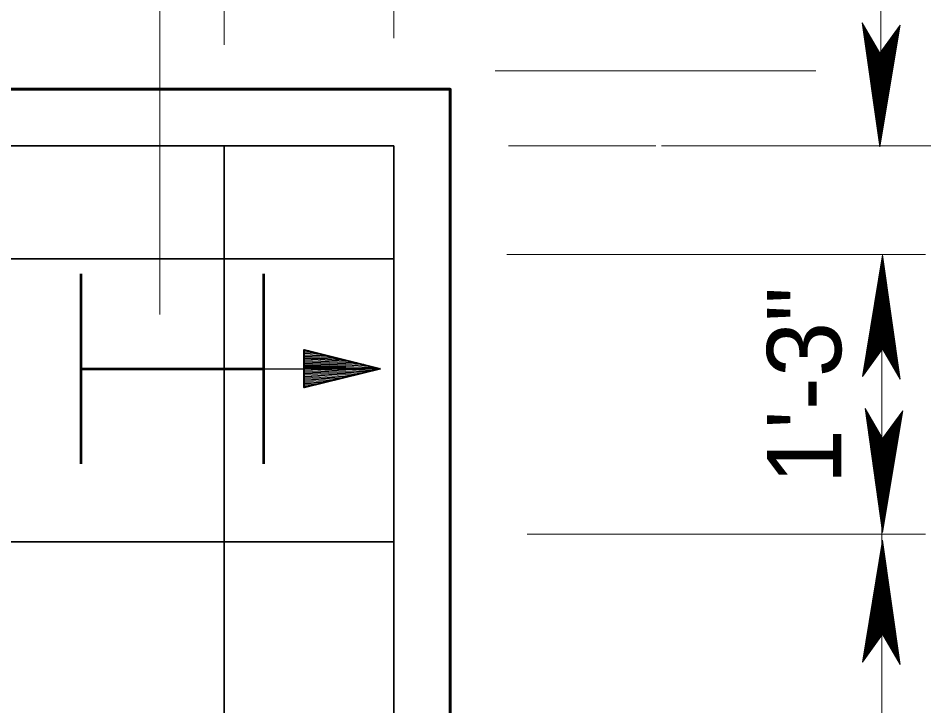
# Model space of a CAD drawing. Extents: x 144 to 252, y 360 to 425.
# Drawn here: x 178.494 to 182.528, y 377.06 to 380.098 of the extents above; entities that cross this region are included whole.
import ezdxf
from ezdxf.enums import TextEntityAlignment as Align

# ---------------------------------------------------------------- set-up
doc = ezdxf.new("R2010")
doc.units = 0
doc.header["$LTSCALE"] = 0.13
for name, color, linetype, lineweight in [('1', 7, 'Continuous', 40), ('10', 7, 'Continuous', 35), ('16', 7, 'Continuous', 13), ('3', 7, 'Continuous', 13), ('9', 7, 'Continuous', 25)]:
    doc.layers.add(name, color=color, linetype=linetype, lineweight=lineweight)

msp = doc.modelspace()

# ---------------------------------------------------------------- linework, layer by layer
at = {"layer": '1', "lineweight": 13}
for p, q in [((182.3068, 379.6502), (182.3068, 380.8135)), ((182.3109, 379.5948), (182.3109, 379.9001)), ((182.0191, 379.866), (180.6024, 379.866)), ((181.3125, 379.5348), (180.6607, 379.5348)), ((182.5277, 379.5348), (181.3369, 379.5348)), ((182.5048, 379.0537), (180.6533, 379.0537)), ((182.3109, 377.2068), (182.3109, 379.0183)), ((182.5048, 377.8178), (180.7443, 377.8178)), ((182.3109, 377.2068), (182.3109, 375.7844))]:
    msp.add_line(p, q, dxfattribs=at)
at = {"layer": '1', "lineweight": 60}
for p, q in [((156.4041, 379.7844), (180.4041, 379.7844)), ((156.4041, 379.7844), (180.4041, 379.7844)), ((156.4041, 379.7844), (180.4041, 379.7844)), ((156.4041, 379.7844), (180.4041, 379.7844)), ((180.4041, 379.7844), (180.4041, 377.2068)), ((180.4041, 379.7844), (180.4041, 377.2068)), ((180.4041, 375.7844), (180.4041, 377.2068))]:
    msp.add_line(p, q, dxfattribs=at)
at = {"layer": '1', "lineweight": 35}
for p, q in [((168.4963, 379.5344), (180.1541, 379.5344)), ((179.4041, 377.2068), (179.4041, 379.5344)), ((168.5137, 379.0344), (180.1541, 379.0344)), ((168.5137, 377.7844), (180.1541, 377.7844)), ((179.4041, 377.2068), (179.4041, 375.7844))]:
    msp.add_line(p, q, dxfattribs=at)
at = {"layer": '1', "lineweight": 53}
for p, q in [((178.7721, 378.1291), (178.7721, 378.9687)), ((179.5804, 378.1292), (179.5804, 378.9688)), ((178.7721, 378.5489), (179.5804, 378.5489))]:
    msp.add_line(p, q, dxfattribs=at)
at = {"layer": '1', "lineweight": 25}
msp.add_line((179.5804, 378.5489), (180.0804, 378.5489), dxfattribs=at)
at = {"layer": '1', "lineweight": 60}
msp.add_lwpolyline([(156.4041, 379.7844), (180.4041, 379.7844), (180.4041, 369.7844)], dxfattribs=at)
at = {"layer": '1', "lineweight": 35}
msp.add_lwpolyline([(180.1541, 375.7844), (180.1541, 377.2068), (180.1541, 379.5344)], dxfattribs=at)
at = {"layer": '10'}
for p, q in [((179.7583, 378.5971), (179.9308, 378.5898)), ((179.9422, 378.5643), (179.7583, 378.5719)), ((179.9421, 378.5579), (179.7583, 378.5657)), ((179.7583, 378.5593), (179.9419, 378.5517)), ((179.9417, 378.5454), (179.7583, 378.5531)), ((179.7583, 378.5493), (180.0935, 378.5493))]:
    msp.add_line(p, q, dxfattribs=at)
for points in [[(179.7583, 378.4658), (179.7583, 378.6327), (180.0935, 378.5494)], [(179.7583, 378.4658), (180.0935, 378.5494), (179.7583, 378.4658)]]:
    msp.add_lwpolyline(points, dxfattribs=at)
msp.add_lwpolyline([(180.0935, 378.5494), (179.7583, 378.4658), (179.7583, 378.6327), (179.7583, 378.4658)], close=True, dxfattribs=at)
at = {"layer": '3'}
for p, q in [((179.1199, 378.7893), (179.1199, 381.2715)), ((179.4041, 379.9803), (179.4041, 381.191)), ((180.1541, 380.0104), (180.1541, 380.8482)), ((182.2248, 380.0777), (182.3026, 379.529)), ((182.3028, 379.9442), (182.2248, 380.0777)), ((182.2283, 380.0718), (182.3032, 379.5434)), ((182.2303, 380.0682), (182.3032, 379.5542)), ((182.233, 380.0637), (182.3032, 379.5687)), ((182.2354, 380.0596), (182.3032, 379.5814)), ((182.2354, 380.0596), (182.3032, 379.5814)), ((182.2376, 380.0559), (182.3032, 379.5927)), ((182.3026, 379.529), (182.3918, 380.0667)), ((182.3918, 380.0667), (182.3028, 379.9442)), ((182.3032, 379.5434), (182.3895, 380.0634)), ((182.3032, 379.5542), (182.3872, 380.0602)), ((182.3032, 379.5687), (182.384, 380.0559)), ((182.3032, 379.5814), (182.3813, 380.0522)), ((182.2403, 380.0513), (182.3032, 379.6072)), ((182.2427, 380.0472), (182.3032, 379.6199)), ((182.2452, 380.0428), (182.3032, 379.6337)), ((182.2477, 380.0384), (182.3032, 379.6475)), ((182.2502, 380.0342), (182.3032, 379.6608)), ((182.2529, 380.0297), (182.3032, 379.6747)), ((182.2552, 380.0257), (182.3032, 379.6873)), ((182.2574, 380.0219), (182.3032, 379.6987)), ((182.2602, 380.0169), (182.3032, 379.7143)), ((182.2629, 380.0125), (182.3032, 379.7282)), ((182.3032, 379.5927), (182.3789, 380.0488)), ((182.3032, 379.6072), (182.3757, 380.0446)), ((182.3032, 379.6199), (182.373, 380.0408)), ((182.3032, 379.6337), (182.3701, 380.0367)), ((182.3032, 379.6475), (182.3671, 380.0327)), ((182.3032, 379.6608), (182.3642, 380.0288)), ((182.3032, 379.6747), (182.3612, 380.0247)), ((182.3032, 379.6873), (182.3586, 380.0209)), ((182.3032, 379.6987), (182.3561, 380.0175)), ((182.3032, 379.7143), (182.3527, 380.0129)), ((182.2652, 380.0085), (182.3022, 379.7477)), ((182.2671, 380.0053), (182.3038, 379.7462)), ((182.2697, 380.0009), (182.3038, 379.7601)), ((182.2722, 379.9967), (182.3038, 379.7732)), ((182.273, 379.9952), (182.3032, 379.7823)), ((182.2752, 379.9912), (182.3032, 379.7943)), ((182.2779, 379.9868), (182.3032, 379.8082)), ((182.2807, 379.9818), (182.3032, 379.8238)), ((182.2832, 379.9778), (182.3032, 379.8364)), ((182.2857, 379.9735), (182.3032, 379.8497)), ((182.3032, 379.7282), (182.3498, 380.0088)), ((182.3032, 379.7823), (182.3381, 379.9928)), ((182.3032, 379.7943), (182.3355, 379.9892)), ((182.3032, 379.8082), (182.3325, 379.9852)), ((182.3032, 379.8238), (182.3293, 379.9805)), ((182.3032, 379.8364), (182.3265, 379.9768)), ((182.3032, 379.8497), (182.3237, 379.9729)), ((182.3038, 379.7462), (182.3467, 380.0046)), ((182.3038, 379.7601), (182.3437, 380.0004)), ((182.3038, 379.7732), (182.3408, 379.9966)), ((182.2879, 379.9697), (182.3032, 379.8617)), ((182.2906, 379.965), (182.3032, 379.8762)), ((182.2932, 379.9606), (182.3032, 379.89)), ((182.2955, 379.9565), (182.3032, 379.9027)), ((182.2986, 379.9512), (182.3022, 379.9262)), ((182.3002, 379.9486), (182.3032, 379.9273)), ((182.3026, 379.9444), (182.3026, 379.529)), ((182.3032, 379.8617), (182.321, 379.9693)), ((182.3032, 379.8762), (182.318, 379.9651)), ((182.3032, 379.89), (182.315, 379.9609)), ((182.3032, 379.9027), (182.3123, 379.9572)), ((182.3032, 379.9159), (182.3094, 379.9533)), ((182.3032, 379.9273), (182.307, 379.9499)), ((182.3032, 379.9375), (182.3047, 379.9469)), ((182.3148, 379.0521), (182.2256, 378.5144)), ((182.3148, 378.6367), (182.3148, 379.0521)), ((182.3926, 378.5033), (182.3148, 379.0521)), ((182.3142, 379.0377), (182.2279, 378.5177)), ((182.3142, 379.0268), (182.2302, 378.5209)), ((182.3142, 379.0124), (182.2334, 378.5252)), ((182.3891, 378.5093), (182.3142, 379.0377)), ((182.3871, 378.5128), (182.3142, 379.0268)), ((182.3844, 378.5174), (182.3142, 379.0124)), ((182.3142, 378.9997), (182.2361, 378.5289)), ((182.3142, 378.9883), (182.2385, 378.5322)), ((182.3142, 378.9739), (182.2417, 378.5365)), ((182.382, 378.5215), (182.3142, 378.9997)), ((182.382, 378.5215), (182.3142, 378.9997)), ((182.3798, 378.5252), (182.3142, 378.9883)), ((182.3772, 378.5297), (182.3142, 378.9739)), ((182.3142, 378.9612), (182.2444, 378.5403)), ((182.3142, 378.9474), (182.2473, 378.5443)), ((182.3142, 378.9336), (182.2503, 378.5484)), ((182.3748, 378.5338), (182.3142, 378.9612)), ((182.3722, 378.5383), (182.3142, 378.9474)), ((182.3697, 378.5427), (182.3142, 378.9336)), ((182.3142, 378.9203), (182.2532, 378.5523)), ((182.3142, 378.9064), (182.2562, 378.5564)), ((182.3142, 378.8938), (182.2588, 378.5602)), ((182.3142, 378.8824), (182.2613, 378.5636)), ((182.3672, 378.5469), (182.3142, 378.9203)), ((182.3645, 378.5514), (182.3142, 378.9064)), ((182.3622, 378.5554), (182.3142, 378.8938)), ((182.36, 378.5592), (182.3142, 378.8824)), ((182.3142, 378.8667), (182.2647, 378.5682)), ((182.3142, 378.8529), (182.2677, 378.5722)), ((182.3572, 378.5642), (182.3142, 378.8667)), ((182.3545, 378.5686), (182.3142, 378.8529)), ((182.3137, 378.8349), (182.2707, 378.5765)), ((182.3137, 378.821), (182.2738, 378.5807)), ((182.3137, 378.8078), (182.2766, 378.5845)), ((182.3503, 378.5757), (182.3137, 378.8349)), ((182.3477, 378.5802), (182.3137, 378.821)), ((182.3452, 378.5844), (182.3137, 378.8078)), ((182.3522, 378.5726), (182.3152, 378.8333)), ((182.3142, 378.7987), (182.2793, 378.5882)), ((182.3142, 378.7867), (182.2819, 378.5918)), ((182.3142, 378.7729), (182.2849, 378.5959)), ((182.3444, 378.5859), (182.3142, 378.7987)), ((182.3422, 378.5898), (182.3142, 378.7867)), ((182.3395, 378.5942), (182.3142, 378.7729)), ((182.3142, 378.7572), (182.2882, 378.6006)), ((182.3142, 378.7447), (182.2909, 378.6042)), ((182.3142, 378.7314), (182.2937, 378.6082)), ((182.3367, 378.5992), (182.3142, 378.7572)), ((182.3342, 378.6033), (182.3142, 378.7447)), ((182.3317, 378.6076), (182.3142, 378.7314)), ((182.3142, 378.7194), (182.2964, 378.6117)), ((182.3142, 378.7049), (182.2994, 378.616)), ((182.3142, 378.6911), (182.3024, 378.6202)), ((182.3295, 378.6114), (182.3142, 378.7194)), ((182.3268, 378.6161), (182.3142, 378.7049)), ((182.3243, 378.6205), (182.3142, 378.6911)), ((182.3142, 378.6784), (182.3052, 378.6238)), ((182.3142, 378.6652), (182.308, 378.6277)), ((182.3142, 378.6538), (182.3104, 378.6312)), ((182.3142, 378.6436), (182.3127, 378.6342)), ((182.3219, 378.6246), (182.3142, 378.6784)), ((182.3173, 378.6325), (182.3142, 378.6538)), ((182.3188, 378.6298), (182.3152, 378.6549)), ((182.2256, 378.5144), (182.3147, 378.6369)), ((182.3147, 378.6369), (182.3926, 378.5033)), ((182.2371, 378.3739), (182.3148, 377.8252)), ((182.315, 378.2403), (182.2371, 378.3739)), ((182.2406, 378.3679), (182.3155, 377.8396)), ((182.2426, 378.3644), (182.3155, 377.8504)), ((182.2452, 378.3598), (182.3155, 377.8648)), ((182.3148, 377.8252), (182.4041, 378.3628)), ((182.4041, 378.3628), (182.315, 378.2403)), ((182.3155, 377.8396), (182.4017, 378.3596)), ((182.2477, 378.3558), (182.3155, 377.8776)), ((182.2477, 378.3558), (182.3155, 377.8776)), ((182.2498, 378.3521), (182.3155, 377.8889)), ((182.2525, 378.3475), (182.3155, 377.9033)), ((182.2549, 378.3434), (182.3155, 377.9161)), ((182.2574, 378.339), (182.3155, 377.9298)), ((182.26, 378.3346), (182.3155, 377.9437)), ((182.2625, 378.3303), (182.3155, 377.9569)), ((182.2652, 378.3258), (182.3155, 377.9708)), ((182.2674, 378.3218), (182.3155, 377.9834)), ((182.2697, 378.3181), (182.3155, 377.9948)), ((182.3155, 377.8504), (182.3994, 378.3563)), ((182.3155, 377.8648), (182.3962, 378.3521)), ((182.3155, 377.8776), (182.3936, 378.3483)), ((182.3155, 377.8889), (182.3912, 378.345)), ((182.3155, 377.9033), (182.388, 378.3408)), ((182.3155, 377.9161), (182.3852, 378.337)), ((182.3155, 377.9298), (182.3823, 378.3329)), ((182.3155, 377.9437), (182.3793, 378.3288)), ((182.3155, 377.9569), (182.3765, 378.3249)), ((182.3155, 377.9708), (182.3735, 378.3208)), ((182.2725, 378.3131), (182.3155, 378.0105)), ((182.2752, 378.3087), (182.3155, 378.0243)), ((182.2774, 378.3047), (182.3144, 378.0439)), ((182.2793, 378.3015), (182.316, 378.0423)), ((182.2819, 378.2971), (182.316, 378.0562)), ((182.2844, 378.2928), (182.316, 378.0694)), ((182.2852, 378.2913), (182.3155, 378.0785)), ((182.2875, 378.2874), (182.3155, 378.0905)), ((182.2902, 378.283), (182.3155, 378.1043)), ((182.293, 378.278), (182.3155, 378.12)), ((182.3155, 377.9834), (182.3708, 378.3171)), ((182.3155, 377.9948), (182.3683, 378.3137)), ((182.3155, 378.0105), (182.365, 378.3091)), ((182.3155, 378.0243), (182.362, 378.305)), ((182.3155, 378.0785), (182.3503, 378.289)), ((182.3155, 378.0905), (182.3477, 378.2854)), ((182.3155, 378.1043), (182.3448, 378.2813)), ((182.316, 378.0423), (182.3589, 378.3007)), ((182.316, 378.0562), (182.3559, 378.2966)), ((182.316, 378.0694), (182.3531, 378.2928)), ((182.2954, 378.2739), (182.3155, 378.1326)), ((182.2979, 378.2697), (182.3155, 378.1458)), ((182.3002, 378.2658), (182.3155, 378.1578)), ((182.3028, 378.2612), (182.3155, 378.1723)), ((182.3054, 378.2568), (182.3155, 378.1862)), ((182.3077, 378.2527), (182.3155, 378.1988)), ((182.3108, 378.2474), (182.3144, 378.2223)), ((182.3124, 378.2448), (182.3155, 378.2235)), ((182.3148, 378.2406), (182.3148, 377.8252)), ((182.3155, 378.12), (182.3415, 378.2767)), ((182.3155, 378.1326), (182.3388, 378.273)), ((182.3155, 378.1458), (182.3359, 378.2691)), ((182.3155, 378.1578), (182.3332, 378.2655)), ((182.3155, 378.1723), (182.3303, 378.2612)), ((182.3155, 378.1862), (182.3272, 378.2571)), ((182.3155, 378.1988), (182.3245, 378.2534)), ((182.3155, 378.2121), (182.3217, 378.2495)), ((182.3155, 378.2235), (182.3192, 378.2461)), ((182.3155, 378.2337), (182.317, 378.2431)), ((182.3148, 377.7911), (182.2256, 377.2534)), ((182.3142, 377.7767), (182.2279, 377.2567)), ((182.3142, 377.7658), (182.2302, 377.2599)), ((182.3891, 377.2483), (182.3142, 377.7767)), ((182.3871, 377.2518), (182.3142, 377.7658)), ((182.3148, 377.3757), (182.3148, 377.7911)), ((182.3926, 377.2423), (182.3148, 377.7911)), ((182.3142, 377.7514), (182.2334, 377.2642)), ((182.3142, 377.7387), (182.2361, 377.2679)), ((182.3142, 377.7273), (182.2385, 377.2713)), ((182.3142, 377.7129), (182.2417, 377.2755)), ((182.3844, 377.2564), (182.3142, 377.7514)), ((182.382, 377.2605), (182.3142, 377.7387)), ((182.382, 377.2605), (182.3142, 377.7387)), ((182.3798, 377.2642), (182.3142, 377.7273)), ((182.3772, 377.2688), (182.3142, 377.7129)), ((182.3142, 377.7002), (182.2444, 377.2792)), ((182.3142, 377.6864), (182.2473, 377.2833)), ((182.3142, 377.6726), (182.2503, 377.2874)), ((182.3748, 377.2728), (182.3142, 377.7002)), ((182.3722, 377.2772), (182.3142, 377.6864)), ((182.3697, 377.2817), (182.3142, 377.6726)), ((182.3142, 377.6593), (182.2532, 377.2913)), ((182.3142, 377.6454), (182.2562, 377.2954)), ((182.3142, 377.6328), (182.2588, 377.2992)), ((182.3672, 377.2859), (182.3142, 377.6593)), ((182.3645, 377.2904), (182.3142, 377.6454)), ((182.3622, 377.2944), (182.3142, 377.6328)), ((182.3142, 377.6214), (182.2613, 377.3026)), ((182.3142, 377.6058), (182.2647, 377.3072)), ((182.3142, 377.5919), (182.2677, 377.3112)), ((182.36, 377.2982), (182.3142, 377.6214)), ((182.3572, 377.3032), (182.3142, 377.6058)), ((182.3545, 377.3076), (182.3142, 377.5919)), ((182.3137, 377.5739), (182.2707, 377.3155)), ((182.3137, 377.56), (182.2738, 377.3197)), ((182.3503, 377.3148), (182.3137, 377.5739)), ((182.3477, 377.3192), (182.3137, 377.56)), ((182.3522, 377.3116), (182.3152, 377.5723)), ((182.3137, 377.5468), (182.2766, 377.3235)), ((182.3142, 377.5377), (182.2793, 377.3272)), ((182.3142, 377.5257), (182.2819, 377.3308)), ((182.3142, 377.5119), (182.2849, 377.3349)), ((182.3452, 377.3234), (182.3137, 377.5468)), ((182.3444, 377.3249), (182.3142, 377.5377)), ((182.3422, 377.3288), (182.3142, 377.5257)), ((182.3395, 377.3332), (182.3142, 377.5119)), ((182.3142, 377.4962), (182.2882, 377.3396)), ((182.3142, 377.4837), (182.2909, 377.3433)), ((182.3142, 377.4704), (182.2937, 377.3472)), ((182.3367, 377.3382), (182.3142, 377.4962)), ((182.3342, 377.3423), (182.3142, 377.4837)), ((182.3317, 377.3466), (182.3142, 377.4704)), ((182.3142, 377.4584), (182.2964, 377.3508)), ((182.3142, 377.4439), (182.2994, 377.355)), ((182.3142, 377.4301), (182.3024, 377.3592)), ((182.3295, 377.3504), (182.3142, 377.4584)), ((182.3268, 377.3551), (182.3142, 377.4439)), ((182.3243, 377.3595), (182.3142, 377.4301)), ((182.3142, 377.4174), (182.3052, 377.3628)), ((182.3142, 377.4042), (182.308, 377.3667)), ((182.3142, 377.3927), (182.3104, 377.3702)), ((182.3219, 377.3636), (182.3142, 377.4174)), ((182.3173, 377.3715), (182.3142, 377.3927)), ((182.3188, 377.3688), (182.3152, 377.3939)), ((182.2256, 377.2534), (182.3147, 377.3759)), ((182.3142, 377.3826), (182.3127, 377.3732)), ((182.3147, 377.3759), (182.3926, 377.2423))]:
    msp.add_line(p, q, dxfattribs=at)
at = {"layer": '9'}
for p, q in [((179.7789, 378.6277), (179.7583, 378.6285)), ((179.8092, 378.6201), (179.7583, 378.6223)), ((179.8397, 378.6125), (179.7583, 378.6159)), ((179.8701, 378.605), (179.7583, 378.6097)), ((179.9005, 378.5974), (179.7583, 378.6034)), ((179.9427, 378.5831), (179.7583, 378.5908)), ((179.9425, 378.5768), (179.7583, 378.5845)), ((179.9423, 378.5705), (179.7583, 378.5782)), ((180.0524, 378.5596), (179.9422, 378.5643)), ((180.022, 378.5672), (179.9423, 378.5705)), ((179.9917, 378.5747), (179.9425, 378.5768)), ((179.9613, 378.5823), (179.9427, 378.5831)), ((179.9416, 378.5391), (179.7583, 378.5467)), ((179.9414, 378.5328), (179.7583, 378.5405)), ((179.9412, 378.5265), (179.7583, 378.5342)), ((179.9411, 378.5202), (179.7583, 378.5279)), ((179.9409, 378.514), (179.7583, 378.5216)), ((179.9715, 378.519), (179.9411, 378.5202)), ((179.9931, 378.5244), (179.9412, 378.5265)), ((180.0147, 378.5297), (179.9414, 378.5328)), ((180.0362, 378.5352), (179.9416, 378.5391)), ((180.0578, 378.5405), (179.9417, 378.5454)), ((180.0795, 378.5459), (179.9419, 378.5517)), ((180.0828, 378.5521), (179.9421, 378.5579)), ((179.9282, 378.5082), (179.7583, 378.5153)), ((179.9067, 378.5028), (179.7583, 378.5091)), ((179.8851, 378.4975), (179.7583, 378.5027)), ((179.8635, 378.4921), (179.7583, 378.4964)), ((179.8419, 378.4867), (179.7583, 378.4902)), ((179.8203, 378.4813), (179.7583, 378.4839)), ((179.9498, 378.5137), (179.9409, 378.514)), ((179.7987, 378.4759), (179.7583, 378.4776)), ((179.7771, 378.4705), (179.7583, 378.4713))]:
    msp.add_line(p, q, dxfattribs=at)
at = {"layer": '9', "lineweight": 40}
msp.add_lwpolyline([(180.0935, 378.5494), (179.7583, 378.4658), (179.7583, 378.6327)], close=True, dxfattribs=at)

# ---------------------------------------------------------------- texts
at = {"layer": '16'}
msp.add_text('1\'-3"', height=0.3281, rotation=90, dxfattribs=at).set_placement((182.1318, 378.4752), align=Align.CENTER)

doc.saveas('drawing.dxf')
